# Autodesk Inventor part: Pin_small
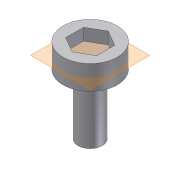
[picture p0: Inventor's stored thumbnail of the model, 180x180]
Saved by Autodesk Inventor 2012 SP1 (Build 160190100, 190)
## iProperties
Created: 2006-09
Part Number: Pin_small
Document SubType Name: Modeling
Mass: 0.333367 g
Surface Area: 4.01996 cm^2
Volume: 0.333367 cm^3
Density: 1 g/cm^3
Material: Default
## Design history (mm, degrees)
sketch "Sketch1"
  geometry: C1 r 2 at (0, 0); 1 further point
  constraints: 1 centre point, 1 coincident
  dimensions: "d0" = 4 diameter of C1
extrude "Extrusion1" new body sketch "Sketch1" distance "d1" = 12; taper "d2" = 0 deg
workplane "Work Plane1"
sketch "Sketch2"
  geometry: C1 r 4.5 at (0, 0); 1 further point
  constraints: 1 centre point, 1 coincident
  dimensions: "d3" = 9 diameter of C1
extrude "Extrusion2" join sketch "Sketch2" stored distance "d4" = 4; taper "d5" = 0 deg
sketch "Sketch3"
  geometry: L1 (-2.593, 1.509)-(0.01, 3); L2 (0.01, 3)-(2.603, 1.491); L3 (2.603, 1.491)-(2.593, -1.509); L4 (2.593, -1.509)-(-0.01, -3); L5 (-0.01, -3)-(-2.603, -1.491); L6 (-2.603, -1.491)-(-2.593, 1.509); 2 further points
  constraints: 12 end point, 1 coincident, 13 other
  dimensions: "d7" = 3 distance of L1.start L1.end
extrude "Extrusion3" cut sketch "Sketch3" distance "d8" = 2; taper "d9" = 0 deg
body "Solid1"
other parameters: "d6" = 0
